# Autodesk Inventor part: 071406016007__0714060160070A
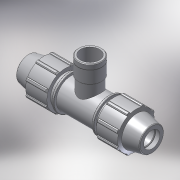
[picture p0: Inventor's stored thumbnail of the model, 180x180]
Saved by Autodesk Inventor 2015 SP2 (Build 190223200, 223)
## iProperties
Created: 2017-02
Part Number: 071406016007__0714060160070A
Material: PVC-Piping
Description: PLASSON TEE WITH THREADED FEMALE OFFTAKE 16-3/4"-16
Document SubType Name: Modeling
Designer: KIM
Mass: 92.6774 g
Surface Area: 199.44 cm^2
Volume: 66.1981 cm^3
Density: 1.4 g/cm^3
Appearance: Smooth - White
Author: KIM
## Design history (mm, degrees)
derived "07140.ipt"
feature "Solid1::07140.ipt"
feature "Solid2::07140.ipt"
tag "TaggingFeature1"
body "Solid1"
other parameters: "d2" = 16, "d4" = 5.08333, "d5" = 14.64, "d7" = 39, "d11" = 2.03333, "d13" = 120 deg, "d14" = 24, "d15" = 12 deg, "d16" = 33.93, "d18" = 0.8, "d19" = 35 deg, "d20" = 17.5 deg, "d21" = 36.27, "d23" = 0, "d25" = 360 deg, "d27" = 0.78, "d33" = 0.32, "d42" = 21.96, "d43" = 1.17, "d46" = 0.48, "d68" = 3.66, "d72" = 41, "d76" = 24.117, "d80" = 0.72351, "d91" = 29.25, "d95" = 14.4, "d112" = 19, "d115" = 30.14625, "d116" = 135 deg, "d117" = 27.73455, "d118" = 122, "d119" = 14.4, "d121" = 0, "d122" = 14.4, "d124" = 0, "d128" = 0, "d129" = 1.6, "d130" = 5.7, "d131" = 0.3, "d132" = 0.3, "d133" = 30.14625, "d_" = 16, "E_" = 39, "A_" = 41, "l_2" = 19, "Rp_" = 24.117, "H_" = 122
